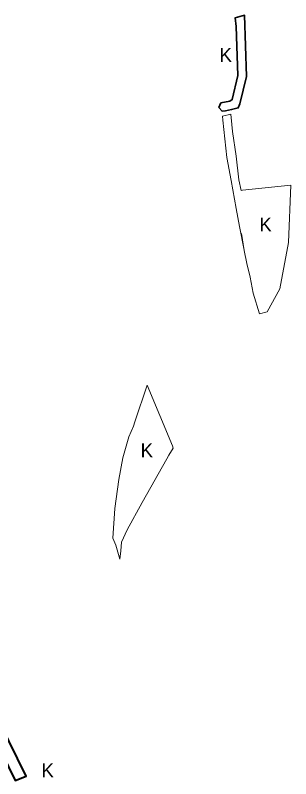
# Model space of a CAD drawing. Extents: x -650276 to -642489, y -1074311 to -1066658.
# Drawn here: x -646145 to -645670, y -1068808 to -1067493 of the extents above; entities that cross this region are included whole.
import ezdxf

# ---------------------------------------------------------------- set-up
doc = ezdxf.new("R2010")
doc.units = 0
doc.header["$LTSCALE"] = 9.6
for name, color, linetype, lineweight in [('44', 7, 'Continuous', 40), ('47', 7, 'Continuous', 13), ('48', 7, 'Continuous', 35), ('5', 7, 'Continuous', 35)]:
    doc.layers.add(name, color=color, linetype=linetype, lineweight=lineweight)
doc.layers.add('58', color=7, linetype='Continuous')

msp = doc.modelspace()

# ---------------------------------------------------------------- linework, layer by layer
at = {"layer": '44'}
msp.add_lwpolyline([(-646305.678, -1068613.404), (-646243.997, -1068647.407), (-646236.707, -1068651.891), (-646228.691, -1068658.051), (-646221.348, -1068665.144), (-646213.659, -1068674.696), (-646209.179, -1068681.795), (-646204.654, -1068690.937), (-646145.083, -1068810.83), (-646126.317, -1068803.654), (-646186.371, -1068682.825)], dxfattribs=at)
at = {"layer": '47'}
for points in [[(-645751.08, -1067894.5), (-645755.058, -1067868.324), (-645750.41, -1067897.81), (-645745.86, -1067920.32), (-645739.85, -1067943.75), (-645734.61, -1067971.28), (-645723.79, -1068007.07), (-645710.519, -1068003.601), (-645688.88, -1067964.087), (-645673.827, -1067884.119), (-645670.064, -1067785.335), (-645753.14, -1067793.982), (-645755.758, -1067794.254), (-645759.32, -1067775.89), (-645763.92, -1067735.14), (-645770.39, -1067692.63), (-645771.86, -1067680.92), (-645773.23, -1067662.67), (-645787.55, -1067666.46), (-645787.165, -1067673.232), (-645780.39, -1067737.84), (-645773.04, -1067777.35), (-645773.04, -1067777.35), (-645764.11, -1067825.26), (-645758.47, -1067856.55)], [(-645874.15, -1068234.44), (-645917.44, -1068129.99), (-645938.87, -1068193.06), (-645941.41, -1068200.54), (-645949.52, -1068218.72), (-645959.76, -1068255.23), (-645966.56, -1068292.38), (-645973.25, -1068342.08), (-645976.63, -1068393.14), (-645971.94, -1068405.38), (-645964.53, -1068429.83), (-645963.12, -1068415.21), (-645961.7, -1068400.54), (-645952.21, -1068378.95), (-645926.06, -1068332.18), (-645883.87, -1068256.88), (-645880.28, -1068250.47), (-645872.64, -1068238.08)]]:
    msp.add_lwpolyline(points, close=True, dxfattribs=at)
at = {"layer": '5'}
for points in [[(-645757.79, -1067645.206), (-645746.448, -1067597.944), (-645749.67, -1067492.54), (-645765.859, -1067496.872), (-645764.084, -1067511.925), (-645761.499, -1067596.501), (-645770.809, -1067637.786), (-645775.114, -1067640.43), (-645790.381, -1067643.17)], [(-645790.381, -1067643.17), (-645793.94, -1067651.61), (-645788.395, -1067658.038), (-645782.72, -1067657.28), (-645772.13, -1067655.13), (-645760.67, -1067652.05), (-645757.79, -1067645.206)]]:
    msp.add_lwpolyline(points, dxfattribs=at)

# ---------------------------------------------------------------- texts
at = {"layer": '48'}
for p in [(-645724.189, -1067865.057), (-645724.189, -1067865.057), (-645928.983, -1068254.123), (-645928.983, -1068254.123), (-646099.972, -1068805.526)]:
    msp.add_text('K', height=24, dxfattribs=at).set_placement(p)
at = {"layer": '58'}
msp.add_text('K', height=24, dxfattribs=at).set_placement((-645792.887, -1067572.893))

doc.saveas('drawing.dxf')
